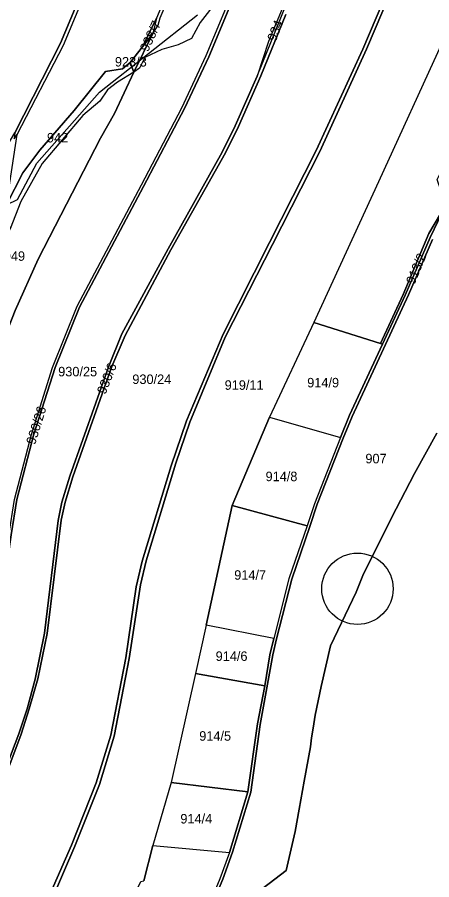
# Model space of a CAD drawing. Extents: x -623250 to -619626, y -1079612 to -1075424.
# Drawn here: x -621459 to -621023, y -1079114 to -1078207 of the extents above; entities that cross this region are included whole.
import ezdxf

# ---------------------------------------------------------------- set-up
doc = ezdxf.new("R2010")
doc.units = 0
for name, color, linetype in [('Bodové pole k revizi', 7, 'Continuous'), ('Cestní síť', 7, 'Continuous'), ('Hranice převzatá (KoPÚ Hrušová)', 7, 'Continuous'), ('Parcela nároku', 7, 'Continuous'), ('Parcelní číslo', 7, 'Continuous')]:
    doc.layers.add(name, color=color, linetype=linetype)

msp = doc.modelspace()

# ---------------------------------------------------------------- linework, layer by layer
at = {"layer": 'Bodové pole k revizi'}
msp.add_circle((-621101.45, -1078807.71), 37.5, dxfattribs=at)
at = {"layer": 'Cestní síť'}
for p, q in [((-621372.5, -1078285.91), (-621269.42, -1078204.38)), ((-621438.28, -1078360.57), (-621372.5, -1078285.91)), ((-621458.59, -1078398.76), (-621438.28, -1078360.57)), ((-621519.46, -1078427.24), (-621458.59, -1078398.76))]:
    msp.add_line(p, q, dxfattribs=at)
at = {"layer": 'Hranice převzatá (KoPÚ Hrušová)'}
msp.add_lwpolyline([(-621017.97, -1078644.2), (-621041.35, -1078686.72), (-621065.51, -1078733.18), (-621095.63, -1078793.63), (-621101.45, -1078807.71), (-621102.97, -1078811.19), (-621129.74, -1078867.81), (-621139.45, -1078910.39), (-621145.88, -1078940.65), (-621148.01, -1078954.17), (-621149.62, -1078964.37), (-621150.89, -1078973.8), (-621157.4, -1079009.9), (-621162.64, -1079039.53), (-621166.75, -1079062.75), (-621176.41, -1079103.88), (-621213.36, -1079132.2)], dxfattribs=at)
at = {"layer": 'Parcela nároku'}
for points in [[(-621287.56, -1077905.65), (-621340.92, -1078060.83), (-621413.47, -1078234.45), (-621461.2, -1078328.4), (-621462.02, -1078334.75), (-621459.02, -1078330.44), (-621410.27, -1078236.51), (-621337.32, -1078062), (-621284.16, -1077906.18), (-621257.6, -1077825.18), (-621204.75, -1077662.32), (-621198.6, -1077626.58), (-621199.7, -1077617.03), (-621206.08, -1077609.32), (-621211.44, -1077608.6), (-621204.6, -1077618.06), (-621201.95, -1077630.34), (-621208.08, -1077659.7), (-621260.76, -1077824.45)], [(-621008.56, -1078404.36), (-621017.73, -1078377.42), (-621002.28, -1078346.64), (-620980.12, -1078309.1), (-620924.03, -1078192.83), (-620909.26, -1078144.65), (-620864.07, -1078024.91), (-620893.6, -1078012.73), (-620921.77, -1077997.49), (-620966.72, -1078114.79), (-621011.6, -1078232.04), (-621079.38, -1078380), (-621147.2, -1078528.01), (-621077.2, -1078550.1), (-621053.41, -1078498.33), (-621026.59, -1078434.43)], [(-621202.73, -1078090.51), (-621194.83, -1078059.97), (-621187.33, -1078043.15), (-621177.33, -1078034.1), (-621203.55, -1078104.44), (-621210.54, -1078112.87), (-621219.88, -1078127.45), (-621233.63, -1078155.71), (-621237.73, -1078169.84), (-621246.01, -1078185.49), (-621266.68, -1078212.76), (-621275.63, -1078229.25), (-621289.76, -1078235.93), (-621307, -1078240.79), (-621324.7, -1078249.3), (-621330.24, -1078260.55), (-621336.49, -1078264.69), (-621316.51, -1078224.27), (-621310.76, -1078215.29), (-621308.79, -1078207.6), (-621267.62, -1078112.37), (-621224.49, -1078106.36), (-621218.77, -1078099.61)], [(-621195.01, -1078232.61), (-621206.9, -1078269.15), (-621191.82, -1078231.8), (-621175.34, -1078191.16), (-621160.87, -1078150.94)], [(-621327.26, -1078238.09), (-621312.71, -1078208.01), (-621316.51, -1078224.27)], [(-621340.16, -1078254.66), (-621327.26, -1078238.09), (-621316.51, -1078224.27), (-621336.49, -1078264.69)], [(-621340.16, -1078254.66), (-621336.49, -1078264.69), (-621353.63, -1078275.14), (-621364.04, -1078283.5), (-621372.09, -1078295.2), (-621389.85, -1078310.39), (-621432.54, -1078360.91), (-621455.01, -1078400.57), (-621466.37, -1078429.55), (-621471.07, -1078408.51), (-621470.26, -1078404.27), (-621452.78, -1078370.63), (-621435.04, -1078346.86), (-621398.92, -1078305.09), (-621366.28, -1078263.93), (-621348.2, -1078261.33)], [(-621364.04, -1078283.5), (-621372.09, -1078295.2), (-621389.85, -1078310.39), (-621432.54, -1078360.91), (-621455.01, -1078400.57), (-621466.37, -1078429.55), (-621476.8, -1078449.26), (-621482.83, -1078456.56), (-621508.49, -1078516.75), (-621525.64, -1078547.69), (-621530.97, -1078565.56), (-621541.52, -1078588.75), (-621482.56, -1078579.03), (-621472.93, -1078545.76), (-621461.05, -1078515.35), (-621436.88, -1078461.43), (-621371.42, -1078334.2), (-621356.58, -1078308.26), (-621336.49, -1078264.69), (-621353.63, -1078275.14)], [(-621053.41, -1078498.33), (-621077.2, -1078550.1), (-621075.27, -1078550.77), (-621051.24, -1078499.07), (-621025.21, -1078438.58), (-621008.56, -1078404.36), (-621026.59, -1078434.43)], [(-621075.27, -1078550.77), (-621077.2, -1078550.1), (-621147.2, -1078528.01), (-621193.76, -1078627.3), (-621119.27, -1078648.59), (-621109.78, -1078625.18)], [(-621193.76, -1078627.3), (-621119.27, -1078648.59), (-621146.42, -1078718.33), (-621154.44, -1078741.43), (-621232.99, -1078720.08)], [(-621260.2, -1078845.86), (-621232.99, -1078720.08), (-621154.44, -1078741.43), (-621173.65, -1078797.26), (-621189.43, -1078859.99)], [(-621260.2, -1078845.86), (-621271.7, -1078896.63), (-621198.81, -1078909.64), (-621193.58, -1078876.99), (-621189.43, -1078859.99)], [(-621271.7, -1078896.63), (-621297.15, -1079011.47), (-621216.55, -1079021.14), (-621206.53, -1078949.76), (-621198.81, -1078909.64)], [(-621297.15, -1079011.47), (-621316.28, -1079077.48), (-621235.86, -1079084.96), (-621216.55, -1079021.14)], [(-621306.43, -1079174.53), (-621305.87, -1079180.47), (-621364.58, -1079190.89), (-621328.86, -1079115.51), (-621325.8, -1079114.53), (-621316.28, -1079077.48), (-621235.86, -1079084.96), (-621246.07, -1079112.51), (-621267.76, -1079164.64), (-621273.35, -1079176.22), (-621299.79, -1079179.67), (-621294.56, -1079171.84)]]:
    msp.add_lwpolyline(points, close=True, dxfattribs=at)
for points in [[(-621554.92, -1078203.35), (-621592.05, -1078275.81), (-621629.4, -1078352.25), (-621646.81, -1078392.15), (-621662.54, -1078434.29), (-621665.37, -1078450.05), (-621657.03, -1078529.12), (-621659.7, -1078554.03), (-621662.04, -1078561.38), (-621647.78, -1078559.79), (-621630.42, -1078529.65), (-621607.54, -1078506.27), (-621586.92, -1078489.2), (-621574.29, -1078475.88), (-621563.17, -1078461.06), (-621534.4, -1078433.79), (-621514.12, -1078417.52), (-621461.2, -1078328.4), (-621413.47, -1078234.45), (-621340.92, -1078060.83)], [(-621270.05, -1078106.95), (-621312.71, -1078208.01), (-621327.26, -1078238.09), (-621340.16, -1078254.66), (-621348.2, -1078261.33), (-621366.28, -1078263.93), (-621398.92, -1078305.09), (-621435.04, -1078346.86), (-621452.78, -1078370.63), (-621470.26, -1078404.27), (-621459.02, -1078330.44), (-621410.27, -1078236.51), (-621337.32, -1078062)], [(-621270.05, -1078106.95), (-621312.71, -1078208.01), (-621316.51, -1078224.27), (-621310.76, -1078215.29), (-621308.79, -1078207.6), (-621267.62, -1078112.37)], [(-621453.32, -1079194.45), (-621401.7, -1079077.19), (-621375.97, -1079011.81), (-621360.34, -1078961.61), (-621344.8, -1078880.4), (-621333.82, -1078805.53), (-621327.6, -1078778.68), (-621297.07, -1078678.44), (-621280.95, -1078631.35), (-621242.58, -1078540.03), (-621193.93, -1078443.75), (-621144.98, -1078347.18), (-621095.78, -1078240.75), (-621053.62, -1078141.34)], [(-621053.62, -1078141.34), (-621095.78, -1078240.75), (-621144.98, -1078347.18), (-621193.93, -1078443.75), (-621242.58, -1078540.03), (-621280.95, -1078631.35), (-621297.07, -1078678.44), (-621327.6, -1078778.68), (-621333.82, -1078805.53), (-621344.8, -1078880.4), (-621360.34, -1078961.61), (-621375.97, -1079011.81), (-621401.7, -1079077.19), (-621453.32, -1079194.45)], [(-621049.48, -1078140.79), (-621091.98, -1078240.75), (-621140.94, -1078348), (-621190.77, -1078445.79), (-621240.52, -1078543.41), (-621277.63, -1078632.71), (-621292.27, -1078675.82), (-621323.47, -1078778.49), (-621329.2, -1078803.44), (-621341.14, -1078881.19), (-621357.06, -1078962.52), (-621372.46, -1079013.35), (-621398.17, -1079078.4), (-621449.12, -1079196.35)], [(-621449.12, -1079196.35), (-621398.17, -1079078.4), (-621372.46, -1079013.35), (-621357.06, -1078962.52), (-621341.14, -1078881.19), (-621329.2, -1078803.44), (-621323.47, -1078778.49), (-621292.27, -1078675.82), (-621277.63, -1078632.71), (-621240.52, -1078543.41), (-621190.77, -1078445.79), (-621140.94, -1078348), (-621091.98, -1078240.75), (-621049.48, -1078140.79)], [(-621160.87, -1078150.94), (-621195.01, -1078232.61), (-621206.9, -1078269.15), (-621229.75, -1078321.25), (-621243.59, -1078348.94), (-621300.37, -1078450.53), (-621348.82, -1078539.66), (-621362.78, -1078573.74), (-621403.68, -1078689.33), (-621411.98, -1078716.86), (-621415.88, -1078735.94), (-621430.26, -1078854.44), (-621439.94, -1078902.91), (-621448.54, -1078933.98), (-621457.03, -1078960.26), (-621469.72, -1078993.33), (-621513.27, -1079097.24), (-621553.12, -1079174.98)], [(-621623.35, -1079196.85), (-621581.79, -1079105.62), (-621540.15, -1079014.34), (-621516.01, -1078954.42), (-621493.87, -1078891.2), (-621482.89, -1078844.86), (-621474.78, -1078800.9), (-621467.65, -1078751.76), (-621461.59, -1078713.98), (-621443.98, -1078645.43), (-621421.65, -1078575.29), (-621395.74, -1078510.7), (-621328.21, -1078383.31), (-621285.96, -1078302.34), (-621260.27, -1078247.26), (-621226.36, -1078165.63)], [(-621623.35, -1079196.85), (-621581.79, -1079105.62), (-621540.15, -1079014.34), (-621516.01, -1078954.42), (-621493.87, -1078891.2), (-621482.89, -1078844.86), (-621474.78, -1078800.9), (-621467.65, -1078751.76), (-621461.59, -1078713.98), (-621443.98, -1078645.43), (-621421.65, -1078575.29), (-621395.74, -1078510.7), (-621328.21, -1078383.31), (-621285.96, -1078302.34), (-621260.27, -1078247.26), (-621226.36, -1078165.63)], [(-621620.64, -1079196.85), (-621537.78, -1079014.84), (-621513.43, -1078954.49), (-621491.51, -1078891.26), (-621480.64, -1078845.11), (-621472.29, -1078800.7), (-621465.28, -1078751.09), (-621459.35, -1078714.06), (-621441.33, -1078645.33), (-621418.85, -1078575.15), (-621393.44, -1078511.85), (-621326.06, -1078385.04), (-621282.99, -1078303), (-621257.7, -1078248.55), (-621223.28, -1078165.91)], [(-621223.28, -1078165.91), (-621257.7, -1078248.55), (-621282.99, -1078303), (-621326.06, -1078385.04), (-621393.44, -1078511.85), (-621418.85, -1078575.15), (-621441.33, -1078645.33), (-621459.35, -1078714.06), (-621465.28, -1078751.09), (-621472.29, -1078800.7), (-621480.64, -1078845.11), (-621491.51, -1078891.26), (-621513.43, -1078954.49), (-621537.78, -1079014.84), (-621620.64, -1079196.85)], [(-621246.01, -1078185.49), (-621266.68, -1078212.76), (-621275.63, -1078229.25), (-621289.76, -1078235.93), (-621307, -1078240.79), (-621324.7, -1078249.3), (-621330.24, -1078260.55), (-621336.49, -1078264.69), (-621356.58, -1078308.26), (-621371.42, -1078334.2), (-621436.88, -1078461.43), (-621461.05, -1078515.35), (-621472.93, -1078545.76), (-621482.56, -1078579.03), (-621483.31, -1078581.78), (-621513.7, -1078692.54), (-621522.18, -1078737.53), (-621523.53, -1078762.49), (-621529.55, -1078801.39), (-621550, -1078870.86), (-621596.99, -1078998.76), (-621655.34, -1079131.2)], [(-621553.12, -1079174.98), (-621513.27, -1079097.24), (-621469.72, -1078993.33), (-621457.03, -1078960.26), (-621448.54, -1078933.98), (-621439.94, -1078902.91), (-621430.26, -1078854.44), (-621415.88, -1078735.94), (-621411.98, -1078716.86), (-621403.68, -1078689.33), (-621362.78, -1078573.74), (-621348.82, -1078539.66), (-621300.37, -1078450.53), (-621243.59, -1078348.94), (-621229.75, -1078321.25), (-621206.9, -1078269.15), (-621191.82, -1078231.8), (-621175.34, -1078191.16)], [(-621176.77, -1078204.28), (-621203.04, -1078268.81), (-621226.41, -1078321.97), (-621240.19, -1078349.74), (-621297.32, -1078451.47), (-621345.37, -1078541.61), (-621359.45, -1078574.28), (-621400.31, -1078690.19), (-621408.59, -1078716.87), (-621412.58, -1078735.75), (-621427.47, -1078854.66), (-621437.16, -1078902.52), (-621446.15, -1078934.09), (-621454.65, -1078960.57), (-621466.72, -1078992.45), (-621510.48, -1079097.75), (-621550.74, -1079175.59)], [(-621550.74, -1079175.59), (-621510.48, -1079097.75), (-621466.72, -1078992.45), (-621454.65, -1078960.57), (-621446.15, -1078934.09), (-621437.16, -1078902.52), (-621427.47, -1078854.66), (-621412.58, -1078735.75), (-621408.59, -1078716.87), (-621400.31, -1078690.19), (-621359.45, -1078574.28), (-621345.37, -1078541.61), (-621297.32, -1078451.47), (-621240.19, -1078349.74), (-621226.41, -1078321.97), (-621203.04, -1078268.81), (-621176.77, -1078204.28)], [(-621011.6, -1078232.04), (-621079.38, -1078380), (-621147.2, -1078528.01), (-621193.76, -1078627.3), (-621232.99, -1078720.08), (-621260.2, -1078845.86), (-621271.7, -1078896.63), (-621297.15, -1079011.47), (-621316.28, -1079077.48), (-621325.8, -1079114.53)], [(-621008.56, -1078404.36), (-621025.21, -1078438.58), (-621051.24, -1078499.07), (-621075.27, -1078550.77), (-621109.78, -1078625.18), (-621119.27, -1078648.59), (-621146.42, -1078718.33), (-621154.44, -1078741.43), (-621173.65, -1078797.26), (-621189.43, -1078859.99), (-621193.58, -1078876.99), (-621198.81, -1078909.64), (-621206.53, -1078949.76), (-621216.55, -1079021.14), (-621235.86, -1079084.96), (-621246.07, -1079112.51), (-621267.76, -1079164.64)], [(-621022.44, -1078440.74), (-621047.69, -1078498.84), (-621106.99, -1078626.85), (-621116.58, -1078649.36), (-621143.7, -1078718.73), (-621151.63, -1078742.21), (-621170.22, -1078797.72), (-621186.55, -1078860.52), (-621190.45, -1078877.27), (-621203.81, -1078950.35), (-621213.44, -1079021.63), (-621232.64, -1079084.71), (-621242.98, -1079113.05), (-621264.88, -1079165.77)], [(-621264.88, -1079165.77), (-621242.98, -1079113.05), (-621232.64, -1079084.71), (-621213.44, -1079021.63), (-621203.81, -1078950.35), (-621190.45, -1078877.27), (-621186.55, -1078860.52), (-621170.22, -1078797.72), (-621151.63, -1078742.21), (-621143.7, -1078718.73), (-621116.58, -1078649.36), (-621106.99, -1078626.85), (-621047.69, -1078498.84), (-621022.44, -1078440.74)], [(-621213.36, -1079132.2), (-621176.41, -1079103.88), (-621166.75, -1079062.75), (-621162.64, -1079039.53), (-621157.4, -1079009.9), (-621150.89, -1078973.8), (-621149.62, -1078964.37), (-621148.01, -1078954.17), (-621145.88, -1078940.65), (-621139.45, -1078910.39), (-621129.74, -1078867.81), (-621102.97, -1078811.19), (-621101.45, -1078807.71), (-621095.63, -1078793.63), (-621065.51, -1078733.18), (-621041.35, -1078686.72), (-621017.97, -1078644.2)]]:
    msp.add_lwpolyline(points, dxfattribs=at)

# ---------------------------------------------------------------- texts
at = {"layer": 'Parcelní číslo'}
for s, rotation, p in [('938/7', 65.28744, (-621321.46, -1078244.11)), ('934', 68.42871, (-621187.36, -1078233.32)), ('913/2', 67.50981, (-621041.63, -1078488.72)), ('930/6', 68.54004, (-621366.21, -1078604.05)), ('930/26', 72.8172, (-621440.15, -1078656.94))]:
    msp.add_text(s, height=10, rotation=rotation, dxfattribs=at).set_placement(p)
for s, p in [('923/3', (-621356.22, -1078258.86)), ('942', (-621427.58, -1078338.66)), ('949', (-621472.94, -1078463.07)), ('930/25', (-621415.81, -1078584.49)), ('930/24', (-621337.92, -1078592.53)), ('919/11', (-621240.93, -1078598.63)), ('914/9', (-621154.22, -1078596.09)), ('907', (-621093.09, -1078675.89)), ('914/8', (-621197.98, -1078694.66)), ('914/7', (-621230.89, -1078798.23)), ('914/6', (-621250.41, -1078883.55)), ('914/5', (-621267.65, -1078967.43)), ('914/4', (-621287.47, -1079054.42))]:
    msp.add_text(s, height=10, dxfattribs=at).set_placement(p)

doc.saveas('drawing.dxf')
